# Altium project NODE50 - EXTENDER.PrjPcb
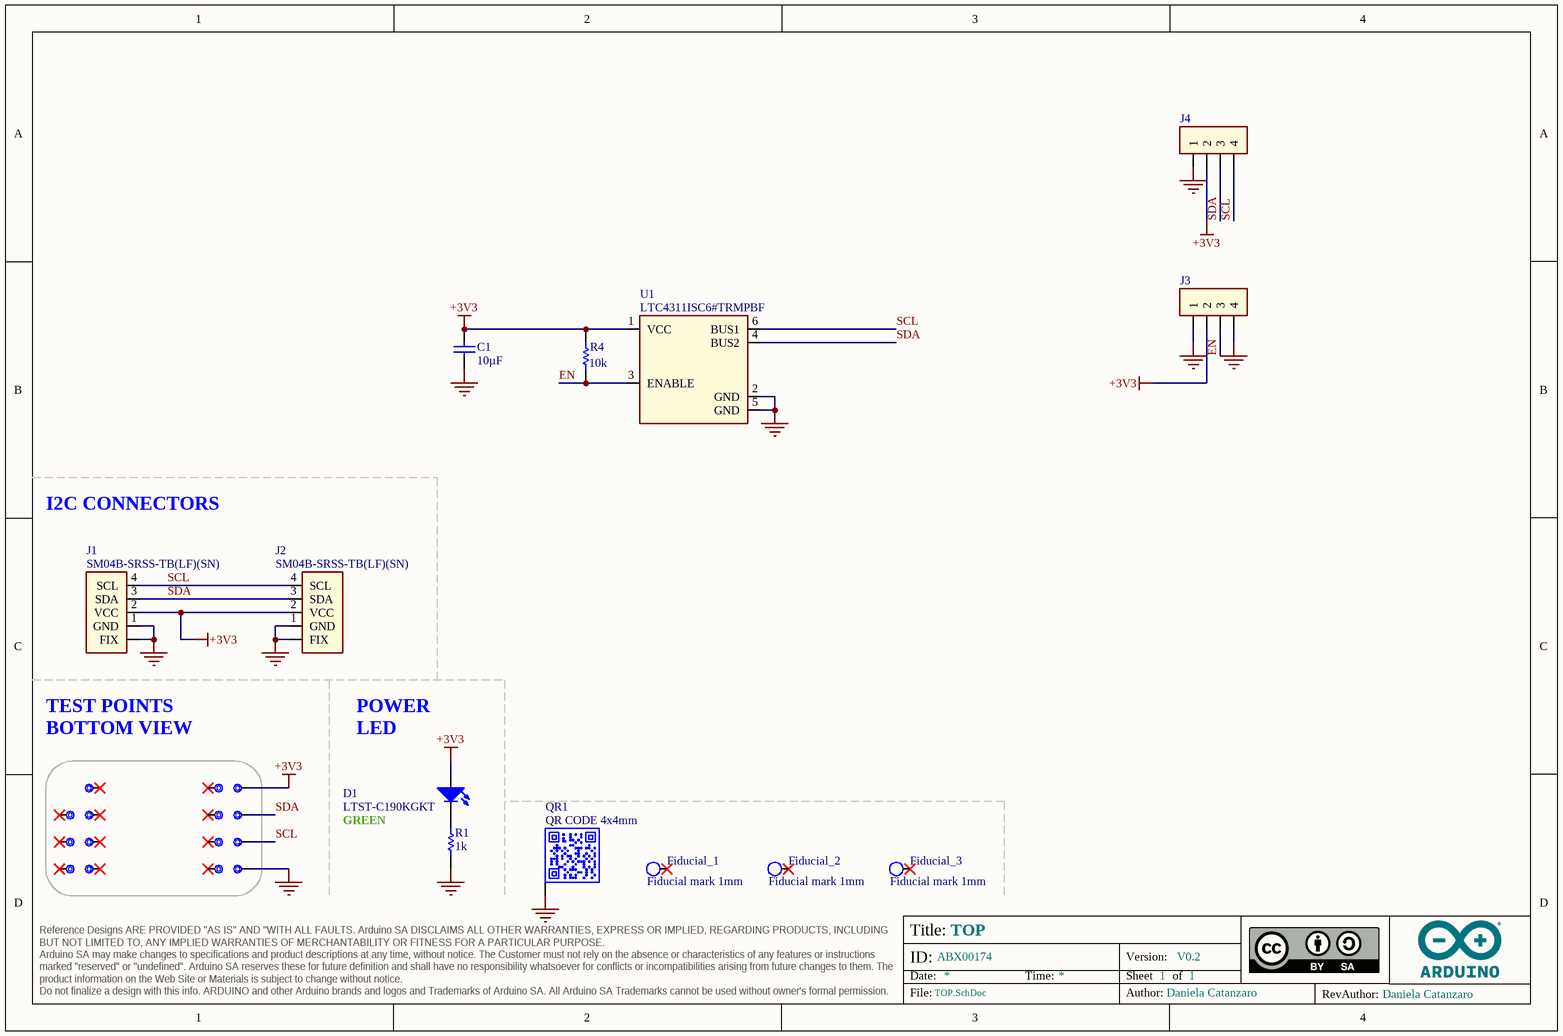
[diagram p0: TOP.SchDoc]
ASSEMBLY_BGA: _; ASSEMBLY_PRESSFIT: _; ASSEMBLY_SMD: X; ASSEMBLY_THT: _; BOARD_CODENAME: NODE50 - EXTENDER; BOARD_INFO_AUTHOR: Daniela Catanzaro; BOARD_INFO_AUTHOR_REV: Daniela Catanzaro; BOARD_INFO_Er: _; BOARD_INFO_FLEX: _; BOARD_INFO_FR4: X; BOARD_INFO_FR4_HTG: _; BOARD_INFO_IPC1: _; BOARD_INFO_IPC2: X; BOARD_INFO_IPC3: _; BOARD_INFO_IPC_NA: _; BOARD_INFO_NUMBER_OF_LAYERS: 2; BOARD_INFO_PCB_SIZE: 41.00x25.36mm; BOARD_INFO_POLYMIDE: _; BOARD_INFO_RIGID: X; BOARD_INFO_RIGID/FLEX: _; BOARD_INFO_TBD: _; BOARD_INFO_THICKNESS: 1.6mm; DRILLS_BLIND: _; DRILLS_BURIED: _; DRILLS_COPPER_FILLING: _; DRILLS_FULL: X; DRILLS_LASER: _; DRILLS_PRESSFIT: _; DRILLS_RESIN_FILLING: _; DRILLS_SLOT: _; DRILLS_SOLDER_FILLING: X; FINISH_ADJUSTMENTS: _; FINISH_EDGE_PLATING: _; FINISH_ENIG: _; FINISH_HAL: _; FINISH_HAL_LF: X; FINISH_NI/AU: _; FINISH_SILK_BOTTOM: X; FINISH_SILK_COLOR: WHITE; FINISH_SILK_TOP: X; FINISH_SN/PB: _; FINISH_SOLDERMASK_BOTTOM: X; FINISH_SOLDERMASK_COLOR: BLUE; FINISH_SOLDERMASK_PEELABLE_BOTTOM: _; FINISH_SOLDERMASK_PEELABLE_COLOR: _; FINISH_SOLDERMASK_PEELABLE_TOP: _; FINISH_SOLDERMASK_TOP: X; FINISH_TABS: _; FINISH_TBD: _; INSULATION_MIN_INNER: 0.15mm; INSULATION_MIN_OUTER: 0.15mm; PANEL_MILLING: X; PANEL_NOT_REQUESTED: _; PANEL_NUMBER_OF_FIGURES: 30; PANEL_PROVIDED: X; PANEL_REQUESTED: _; PANEL_SCORING: X; PANEL_SIZE: 262.00x221.00mm; PANEL_TABS: _; SKU: ABX00174; TRACK_MIN_WIDTH_INNER: 0.15mm; TRACK_MIN_WIDTH_OUTER: 0.15mm; Version: V0.2; VIA_1: _; VIA_1_HOLE_MM: _; VIA_1_PAD_MM: _; VIA_2: _; VIA_2_HOLE_MM: _; VIA_2_PAD_MM: _; VIA_3: _; VIA_3_HOLE_MM: _; VIA_3_PAD_MM: _; VIA_4: _; VIA_4_HOLE_MM: _; VIA_4_PAD_MM: _; VIA_5: _; VIA_5_HOLE_MM: _; VIA_5_PAD_MM: _; VIA_THROUGH: X; VIA_THROUGH_HOLE_MM: 0.3; VIA_THROUGH_PAD_MM: 0.6
1 sheet, 28 parts. Net scope: hierarchical (ports join the sheet entries above them; power ports are global).
Board files: PCB.PcbDoc, PANEL.PcbDoc

## Sheet TOP.SchDoc: TOP
size A4; Revision: V0.2; SheetNumber: 1; SheetTotal: 1

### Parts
3V3  Test point 1.00mm  [TP-1.00MM]  (value not drawn)  (no BOM)
C1  value 10µF  [CAP-0603]  (hidden comment: GRM188R61A106KE69D)
D1  LTST-C190KGKT  [LEDC1608X80N-AK]
Fiducial_1  Fiducial mark 1mm  [Fiducial mark 1mm-Footprint-1]  (no BOM)
Fiducial_2  Fiducial mark 1mm  [Fiducial mark 1mm-Footprint-1]  (no BOM)
Fiducial_3  Fiducial mark 1mm  [Fiducial mark 1mm-Footprint-1]  (no BOM)
GND  Test point 1.00mm  [TP-1.00MM]  (value not drawn)  (no BOM)
J1  SM04B-SRSS-TB(LF)(SN)  [SM04B-SRSS-TB(LF)(SN)-Footprint-1]
J2  SM04B-SRSS-TB(LF)(SN)  [SM04B-SRSS-TB(LF)(SN)-Footprint-1]
J3  HEADER TH 2.54mm VERT. 1x004POS  [PIN HEADER 2.54mm VERT. 1x4POS-Footprint-1]  (value not drawn)  (no BOM)
J4  HEADER TH 2.54mm VERT. 1x004POS  [PIN HEADER 2.54mm VERT. 1x4POS-Footprint-1]  (value not drawn)  (no BOM)
NRST  Test point 1.00mm  [TP-1.00MM]  (value not drawn)  (no BOM)
PA6  Test point 1.00mm  [TP-1.00MM]  (value not drawn)  (no BOM)
PA7  Test point 1.00mm  [TP-1.00MM]  (value not drawn)  (no BOM)
PC14  Test point 1.00mm  [TP-1.00MM]  (value not drawn)  (no BOM)
PC15  Test point 1.00mm  [TP-1.00MM]  (value not drawn)  (no BOM)
QR1  QR CODE 4x4mm  [QR CODE 4x4mm]  (no BOM)
R1  value 1k  [RES-0402]  (hidden comment: CRCW04021K00FKEDC)
R4  value 10k  [RES-0603]  (hidden comment: RC0603FR-0710KL)
SCL  Test point 1.00mm  [TP-1.00MM]  (value not drawn)  (no BOM)
SDA  Test point 1.00mm  [TP-1.00MM]  (value not drawn)  (no BOM)
SWCLK  Test point 1.00mm  [TP-1.00MM]  (value not drawn)  (no BOM)
SWDIO  Test point 1.00mm  [TP-1.00MM]  (value not drawn)  (no BOM)
TP9  Test point 1.00mm  [TP-1.00MM]  (value not drawn)  (no BOM)
TP10  Test point 1.00mm  [TP-1.00MM]  (value not drawn)  (no BOM)
TP11  Test point 1.00mm  [TP-1.00MM]  (value not drawn)  (no BOM)
TP12  Test point 1.00mm  [TP-1.00MM]  (value not drawn)  (no BOM)
U1  LTC4311ISC6#TRMPBF  [SC70 - 6 Leads]

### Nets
+3V3: 3V3.X C1.2 D1.A J1.2(VCC) J2.2(VCC) J3.2 J4.2 R4.2 U1.1(VCC)
GND: C1.1 GND.X J1.1(GND) J1.FIX J2.1(GND) J2.FIX J3.1 J3.4 J4.1 QR1.PAD R1.1 U1.2(GND) U1.5(GND)
EN: J3.3 R4.1 U1.3(ENABLE)  [project net EN_1]
SCL: J1.4(SCL) J2.4(SCL) J4.4 SCL.X U1.6(BUS1)  [project net SCL_1]
SDA: J1.3(SDA) J2.3(SDA) J4.3 SDA.X U1.4(BUS2)  [project net SDA_1]
NetD1_C: D1.C R1.2

Not connected (* = marked no-connect by the designer): Fiducial_1 1*; Fiducial_2 1*; Fiducial_3 1*; NRST X*; PA6 X*; PA7 X*; PC14 X*; PC15 X*; SWCLK X*; SWDIO X*; TP9 X*; TP10 X*; TP11 X*; TP12 X*

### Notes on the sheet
- I2C CONNECTORS
- TEST POINTS BOTTOM VIEW
- (near D1) POWER LED
- GREEN

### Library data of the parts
3V3 GND NRST PA6 PA7 PC14 PC15 SCL SDA SWCLK SWDIO TP9-TP12 = UT0013-A.6: Manufacturer: This is not a component
C1 = C0163-A.1: CAP CHIP 0603 10uF 10% 10V X5R; Manufacturer: Murata; Code Arduino: C0163
D1 = L0009-A.6: LED SMD 0603 GREEN/568 15mcd 120^; Manufacturer: Liteon; Code Arduino: 2204
Fiducial_1-Fiducial_3 = UT0023-A.7: Fiducial mark 1mm clearance 2mm
J1 J2 = J0005-A.3: CONN JST SH 1mm 4POS HORIZONTAL TIN QWIIC; Code Arduino: J0005
J3 J4 = J0162-A.6: Code Arduino: J0162
QR1 = QR-0001-A.5: QR CODE 4x4mm on layer 34 (This is not a component); Code Arduino: QRCODE_4x4mm
R1 = R0007-A.24: RES CHIP 0402 1k 1% 1/16W; Manufacturer: Vishay; Code Arduino: 0140; Power: 62.5mW; Temperature coefficient: 100ppm
R4 = R0292-A.1: RES CHIP 0603 10k 1% 1/10W; Manufacturer: YAGEO; Power: 100mW; Code Arduino: R0292; Temperature coefficient: 100ppm
U1 = U0468-A.1: I2C/SMBus Accelerator, VCC 1.6V-5.5V, SC70 2mm x 2mm; Manufacturer: ANALOG DEVICES; Code Arduino: U0468

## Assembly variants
ABX00174: all parts fitted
